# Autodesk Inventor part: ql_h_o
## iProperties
Created: 2007-11
Part Number: ql_h_o
Document SubType Name: Modeling
Designer: martin
Manufacturer: Standard
Standards Organization: Custom
Author: martin
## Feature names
1. Extrusion3
